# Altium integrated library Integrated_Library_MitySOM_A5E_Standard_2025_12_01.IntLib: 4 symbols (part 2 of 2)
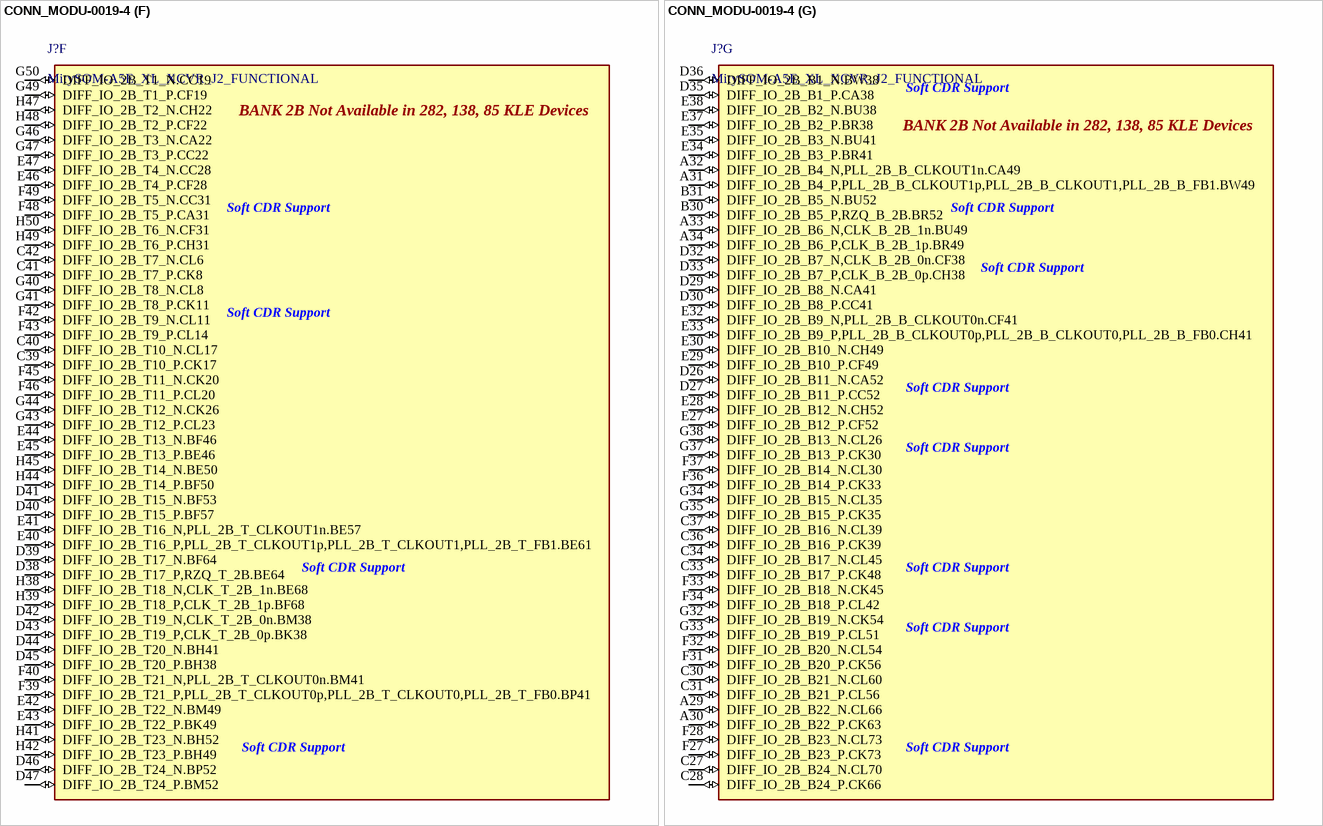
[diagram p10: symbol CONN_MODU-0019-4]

## CONN_MODU-0019-4
designator J?, comment MitySOM-A5E_XL_XCVR_J2_FUNCTIONAL
MitySOM-A5E  XL XCVR Interface Connector, J2, CONN HD ARRAY PLUG 400P SMD GOLD; Manuf 1: Samtec; Manuf 2_PN: SEAM-50-02.0-S-08-2-A-K-TR; Manuf 1_PN: SEAM-50-02.0-L-08-2-A-K-TR; Angle: Vertical; CLPN: 13059
footprint SEAM-50-02.0-S-08-2-A-K-TR (CONN ARRAY SOCKET 400 POS SMD)
part A pins: A01 GND (power), A04 GND (power), A05 GND (power), A08 GND (power), A09 GND (power), A12 GND (power), A13 GND (power), A16 GND (power), A17 GND (power), A20 GND (power), A25 GND (power), A28 GND (power), A35 GND (power), A38 GND (power), A39 GND (power), A42 GND (power), A43 GND (power), A46 GND (power), A47 GND (power), A50 GND (power), B03 GND (power), B06 GND (power), B07 GND (power), B10 GND (power), B11 GND (power), B14 GND (power), B15 GND (power), B18 GND (power), B23 GND (power), B26 GND (power), B29 GND (power), B32 GND (power), B33 GND (power), B36 GND (power), B37 GND (power), B40 GND (power), B41 GND (power), B44 GND (power), B45 GND (power), B48 GND (power), B49 GND (power), B50 GND (power), C01 GND (power), C04 GND (power), C05 GND (power), C08 GND (power), C11 GND (power), C14 GND (power), C17 GND (power), C20 GND (power), C23 GND (power), C26 GND (power), C29 GND (power), C32 GND (power), C35 GND (power), C38 GND (power), C43 GND (power), C46 GND (power), C47 GND (power), C50 GND (power), D03 GND (power), D10 GND (power), D13 GND (power), D16 GND (power), D19 GND (power), D22 GND (power), D25 GND (power), D28 GND (power), D31 GND (power), D34 GND (power), D37 GND (power), D48 GND (power), D49 GND (power), D50 GND (power), E03 GND (power), E06 GND (power), E09 GND (power), E12 GND (power), E15 GND (power), E18 GND (power), E31 GND (power), E36 GND (power), E39 GND (power), E48 GND (power), E49 GND (power), E50 GND (power), F01 GND (power), F08 GND (power), F11 GND (power), F14 GND (power), F17 GND (power), F18 GND (power), F21 GND (power), F22 GND (power), F25 GND (power), F26 GND (power), F29 GND (power), F30 GND (power), F35 GND (power), F38 GND (power), F41 GND (power), F44 GND (power), F47 GND (power), F50 GND (power), G05 GND (power), G08 GND (power), G15 GND (power), G16 GND (power), G19 GND (power), G20 GND (power), G23 GND (power), G24 GND (power), G27 GND (power), G28 GND (power), G31 GND (power), G36 GND (power), G39 GND (power), G42 GND (power), G45 GND (power), G48 GND (power), H02 GND (power), H05 GND (power), H08 GND (power), H11 GND (power), H14 GND (power), H17 GND (power), H18 GND (power), H21 GND (power), H22 GND (power), H25 GND (power), H26 GND (power), H29 GND (power), H30 GND (power), H33 GND (power), H34 GND (power), H37 GND (power), H40 GND (power), H43 GND (power), H46 GND (power)
part B pins: B01 VCCIO_2A (power), B02 VCCIO_2A (power), D01 VCCIO_2A (power), D02 VCCIO_2A (power), E01 VCCIO_2B (power), E02 VCCIO_2B (power), G01 VCCIO_2B (power), G02 VCCIO_2B (power), H01 FAN_EN (in)
part C pins: A02 GTSR4A_TX_CH0_P.BY7 (out), A03 GTSR4A_TX_CH0_N.BY10 (out), A06 GTSR4A_TX_CH1_P.BT7 (out), A07 GTSR4A_TX_CH1_N.BT10 (out), A10 GTSR4A_TX_CH2_P.BL7 (out), A11 GTSR4A_TX_CH2_N.BL10 (out), A14 GTSR4A_TX_CH3_P.BG7 (out), A15 GTSR4A_TX_CH3_N.BG10 (out), A18 REFCLK_GTSR4A_CH1_P.BB16 (in), A19 REFCLK_GTSR4A_CH1_N.BB21 (in), A36 GTSR4C_TX_CH0_P.AU7 (out), A37 GTSR4C_TX_CH0_N.AU10 (out), A40 GTSR4C_TX_CH1_P.AR7 (out), A41 GTSR4C_TX_CH1_N.AR10 (out), A44 GTSR4C_TX_CH2_P.AN7 (out), A45 GTSR4C_TX_CH2_N.AN10 (out), A48 GTSR4C_TX_CH3_P.AL7 (out), A49 GTSR4C_TX_CH3_N.AL10 (out), B04 GTSR4A_RX_CH0_P.CB1 (in), B05 GTSR4A_RX_CH0_N.CB3 (in), B08 GTSR4A_RX_CH1_P.BV1 (in), B09 GTSR4A_RX_CH1_N.BV3 (in), B12 GTSR4A_RX_CH2_P.BN1 (in), B13 GTSR4A_RX_CH2_N.BN3 (in), B16 GTSR4A_RX_CH3_P.BJ1 (in), B17 GTSR4A_RX_CH3_N.BJ3 (in), B34 GTSR4C_RX_CH0_P.AV1 (in), B35 GTSR4C_RX_CH0_N.AV3 (in), B38 GTSR4C_RX_CH1_P.AT1 (in), B39 GTSR4C_RX_CH1_N.AT3 (in), B42 GTSR4C_RX_CH2_P.AP1 (in), B43 GTSR4C_RX_CH2_N.AP3 (in), B46 GTSR4C_RX_CH3_P.AM1 (in), B47 GTSR4C_RX_CH3_N.AM3 (in), C02 REFCLK_GTSR4A_RX_P.BC29 (in), C03 REFCLK_GTSR4A_RX_N.BC25 (in), C44 REFCLK_GTSR4C_RX_P.AT16 (in), C45 REFCLK_GTSR4C_RX_N.AT21 (in), C48 REFCLK_GTSR4C_CH1_P.AP16 (in), C49 REFCLK_GTSR4C_CH1_N.AP21 (in), G17 GTSR4B_RX_CH0_P.BF1 (in), G18 GTSR4B_RX_CH0_N.BF3 (in), G21 GTSR4B_RX_CH1_P.BD1 (in), G22 GTSR4B_RX_CH1_N.BD3 (in), G25 GTSR4B_RX_CH2_P.BB1 (in), G26 GTSR4B_RX_CH2_N.BB3 (in), G29 GTSR4B_RX_CH3_P.AY1 (in), G30 GTSR4B_RX_CH3_N.AY3 (in), H15 REFCLK_GTSR4B_RX_P.AY16 (in), H16 REFCLK_GTSR4B_RX_N.AY21 (in), H19 GTSR4B_TX_CH0_P.BE7 (out), H20 GTSR4B_TX_CH0_N.BE10 (out), H23 GTSR4B_TX_CH1_P.BC7 (out), H24 GTSR4B_TX_CH1_N.BC10 (out), H27 GTSR4B_TX_CH2_P.BA7 (out), H28 GTSR4B_TX_CH2_N.BA10 (out), H31 GTSR4B_TX_CH3_P.AW7 (out), H32 GTSR4B_TX_CH3_N.AW10 (out), H35 REFCLK_GTSR4B_CH1_P.AV16 (in), H36 REFCLK_GTSR4B_CH1_N.AV21 (in)
part D pins: A21 DIFF_IO_2A_T2_P.CF62 (io), A22 DIFF_IO_2A_T2_N.CH62 (io), A23 DIFF_IO_2A_T9_N.BR62 (io), A24 DIFF_IO_2A_T9_P.BU62 (io), A26 DIFF_IO_2A_T17_P,RZQ_T_2A.BH69 (io), A27 DIFF_IO_2A_T17_N.BH71 (io), B19 DIFF_IO_2A_T14_N.BH59 (io), B20 DIFF_IO_2A_T14_P.BH62 (io), B21 DIFF_IO_2A_T15_P.BM62 (io), B22 DIFF_IO_2A_T15_N.BP62 (io), B24 DIFF_IO_2A_T16_P,PLL_2A_T_CLKOUT1p,PLL_2A_T_CLKOUT1,PLL_2A_T_FB1.BM69 (io), B25 DIFF_IO_2A_T16_N,PLL_2A_T_CLKOUT1n.BK69 (io), B27 DIFF_IO_2A_T21_N,PLL_2A_T_CLKOUT0n.BF83 (io), B28 DIFF_IO_2A_T21_P,PLL_2A_T_CLKOUT0p,PLL_2A_T_CLKOUT0,PLL_2A_T_FB0.BE83 (io), C15 DIFF_IO_2A_T5_N.CA71 (io), C16 DIFF_IO_2A_T5_P.CC71 (io), C18 DIFF_IO_2A_T10_N.CA69 (io), C19 DIFF_IO_2A_T10_P.BW69 (io), C21 DIFF_IO_2A_T1_P.CF59 (io), C22 DIFF_IO_2A_T1_N.CH59 (io), C24 DIFF_IO_2A_T7_N.CA59 (io), C25 DIFF_IO_2A_T7_P.BW59 (io), D17 DIFF_IO_2A_T11_P.BR71 (io), D18 DIFF_IO_2A_T11_N.BU71 (io), D20 DIFF_IO_2A_T20_N.BE75 (io), D21 DIFF_IO_2A_T20_P.BE79 (io), D23 DIFF_IO_2A_T19_P,CLK_T_2A_0p.BF75 (io), D24 DIFF_IO_2A_T19_N,CLK_T_2A_0n.BF72 (io), E16 DIFF_IO_2A_T13_N.BK59 (io), E17 DIFF_IO_2A_T13_P.BM59 (io), E19 DIFF_IO_2A_T12_P.BR69 (io), E20 DIFF_IO_2A_T12_N.BU69 (io), E21 DIFF_IO_2A_T3_P.CA62 (io), E22 DIFF_IO_2A_T3_N.CC62 (io), E23 DIFF_IO_2A_T23_N.BF90 (io), E24 DIFF_IO_2A_T23_P.BF93 (io), E25 DIFF_IO_2A_T24_N.BE93 (io), E26 DIFF_IO_2A_T24_P.BE96 (io), F15 DIFF_IO_2A_T6_P.CF71 (io), F16 DIFF_IO_2A_T6_N.CH71 (io), F19 DIFF_IO_2A_T4_N.CF69 (io), F20 DIFF_IO_2A_T4_P.CH69 (io), F23 DIFF_IO_2A_T8_N.BR59 (io), F24 DIFF_IO_2A_T8_P.BU59 (io), G11 DIFF_IO_2A_T18_P,CLK_T_2A_1p.BM71 (io), G12 DIFF_IO_2A_T18_N,CLK_T_2A_1n.BP71 (io), G13 DIFF_IO_2A_T22_N.BE86 (io), G14 DIFF_IO_2A_T22_P.BF86 (io)
part E pins: C06 DIFF_IO_2A_B12_N.BU89 (io), C07 DIFF_IO_2A_B12_P.BR89 (io), C09 DIFF_IO_2A_B10_N.CA89 (io), C10 DIFF_IO_2A_B10_P.BW89 (io), C12 DIFF_IO_2A_B15_P.CF81 (io), C13 DIFF_IO_2A_B15_N.CH81 (io), D04 DIFF_IO_2A_B11_P.BR92 (io), D05 DIFF_IO_2A_B11_N.BU92 (io), D06 DIFF_IO_2A_B16_N.CF89 (io), D07 DIFF_IO_2A_B16_P.CH89 (io), D08 DIFF_IO_2A_B3_P.BM81 (io), D09 DIFF_IO_2A_B3_N.BP81 (io), D11 DIFF_IO_2A_B14_P.CA81 (io), D12 DIFF_IO_2A_B14_N.CC81 (io), D14 DIFF_IO_2A_B7_N,CLK_B_2A_0n.CA78 (io), D15 DIFF_IO_2A_B7_P,CLK_B_2A_0p.BW78 (io), E04 DIFF_IO_2A_B5_N.BH92 (io), E05 DIFF_IO_2A_B5_P,RZQ_B_2A.BH89 (io), E07 DIFF_IO_2A_B1_P.BM78 (io), E08 DIFF_IO_2A_B1_N.BK78 (io), E10 DIFF_IO_2A_B13_N.CF78 (io), E11 DIFF_IO_2A_B13_P.CH78 (io), E13 DIFF_IO_2A_B8_N.BU78 (io), E14 DIFF_IO_2A_B8_P.BR78 (io), F02 DIFF_IO_2A_B6_N,CLK_B_2A_1n.BM92 (io), F03 DIFF_IO_2A_B6_P,CLK_B_2A_1p.BP92 (io), F04 DIFF_IO_2A_B4_N,PLL_2A_B_CLKOUT1n.BM89 (io), F05 DIFF_IO_2A_B4_P,PLL_2A_B_CLKOUT1p,PLL_2A_B_CLKOUT1,PLL_2A_B_FB1.BK89 (io), F06 DIFF_IO_2A_B2_P.BH81 (io), F07 DIFF_IO_2A_B2_N.BH78 (io), F09 DIFF_IO_2A_B9_N,PLL_2A_B_CLKOUT0n.BU81 (io), F10 DIFF_IO_2A_B9_P,PLL_2A_B_CLKOUT0p,PLL_2A_B_CLKOUT0,PLL_2A_B_FB0.BR81 (io), F12 DIFF_IO_2A_B17_P.CF92 (io), F13 DIFF_IO_2A_B17_N.CH92 (io), G03 DIFF_IO_2A_B23_N.CL97 (io), G04 DIFF_IO_2A_B23_P.CK97 (io), G06 DIFF_IO_2A_B22_N.CK88 (io), G07 DIFF_IO_2A_B22_P.CL88 (io), G09 DIFF_IO_2A_B18_N.CA92 (io), G10 DIFF_IO_2A_B18_P.CC92 (io), H03 DIFF_IO_2A_B24_N.CK94 (io), H04 DIFF_IO_2A_B24_P.CL91 (io), H06 DIFF_IO_2A_B21_N.CL85 (io), H07 DIFF_IO_2A_B21_P.CK85 (io), H09 DIFF_IO_2A_B20_N.CL82 (io), H10 DIFF_IO_2A_B20_P.CK80 (io), H12 DIFF_IO_2A_B19_P.CK76 (io), H13 DIFF_IO_2A_B19_N.CL76 (io)
part F pins: C39 DIFF_IO_2B_T10_P.CK17 (io), C40 DIFF_IO_2B_T10_N.CL17 (io), C41 DIFF_IO_2B_T7_P.CK8 (io), C42 DIFF_IO_2B_T7_N.CL6 (io), D38 DIFF_IO_2B_T17_P,RZQ_T_2B.BE64 (io), D39 DIFF_IO_2B_T17_N.BF64 (io), D40 DIFF_IO_2B_T15_P.BF57 (io), D41 DIFF_IO_2B_T15_N.BF53 (io), D42 DIFF_IO_2B_T19_N,CLK_T_2B_0n.BM38 (io), D43 DIFF_IO_2B_T19_P,CLK_T_2B_0p.BK38 (io), D44 DIFF_IO_2B_T20_N.BH41 (io), D45 DIFF_IO_2B_T20_P.BH38 (io), D46 DIFF_IO_2B_T24_N.BP52 (io), D47 DIFF_IO_2B_T24_P.BM52 (io), E40 DIFF_IO_2B_T16_P,PLL_2B_T_CLKOUT1p,PLL_2B_T_CLKOUT1,PLL_2B_T_FB1.BE61 (io), E41 DIFF_IO_2B_T16_N,PLL_2B_T_CLKOUT1n.BE57 (io), E42 DIFF_IO_2B_T22_N.BM49 (io), E43 DIFF_IO_2B_T22_P.BK49 (io), E44 DIFF_IO_2B_T13_N.BF46 (io), E45 DIFF_IO_2B_T13_P.BE46 (io), E46 DIFF_IO_2B_T4_P.CF28 (io), E47 DIFF_IO_2B_T4_N.CC28 (io), F39 DIFF_IO_2B_T21_P,PLL_2B_T_CLKOUT0p,PLL_2B_T_CLKOUT0,PLL_2B_T_FB0.BP41 (io), F40 DIFF_IO_2B_T21_N,PLL_2B_T_CLKOUT0n.BM41 (io), F42 DIFF_IO_2B_T9_N.CL11 (io), F43 DIFF_IO_2B_T9_P.CL14 (io), F45 DIFF_IO_2B_T11_N.CK20 (io), F46 DIFF_IO_2B_T11_P.CL20 (io), F48 DIFF_IO_2B_T5_P.CA31 (io), F49 DIFF_IO_2B_T5_N.CC31 (io), G40 DIFF_IO_2B_T8_N.CL8 (io), G41 DIFF_IO_2B_T8_P.CK11 (io), G43 DIFF_IO_2B_T12_P.CL23 (io), G44 DIFF_IO_2B_T12_N.CK26 (io), G46 DIFF_IO_2B_T3_N.CA22 (io), G47 DIFF_IO_2B_T3_P.CC22 (io), G49 DIFF_IO_2B_T1_P.CF19 (io), G50 DIFF_IO_2B_T1_N.CC19 (io), H38 DIFF_IO_2B_T18_N,CLK_T_2B_1n.BE68 (io), H39 DIFF_IO_2B_T18_P,CLK_T_2B_1p.BF68 (io), H41 DIFF_IO_2B_T23_N.BH52 (io), H42 DIFF_IO_2B_T23_P.BH49 (io), H44 DIFF_IO_2B_T14_P.BF50 (io), H45 DIFF_IO_2B_T14_N.BE50 (io), H47 DIFF_IO_2B_T2_N.CH22 (io), H48 DIFF_IO_2B_T2_P.CF22 (io), H49 DIFF_IO_2B_T6_P.CH31 (io), H50 DIFF_IO_2B_T6_N.CF31 (io)
part G pins: A29 DIFF_IO_2B_B22_N.CL66 (io), A30 DIFF_IO_2B_B22_P.CK63 (io), A31 DIFF_IO_2B_B4_P,PLL_2B_B_CLKOUT1p,PLL_2B_B_CLKOUT1,PLL_2B_B_FB1.BW49 (io), A32 DIFF_IO_2B_B4_N,PLL_2B_B_CLKOUT1n.CA49 (io), A33 DIFF_IO_2B_B6_N,CLK_B_2B_1n.BU49 (io), A34 DIFF_IO_2B_B6_P,CLK_B_2B_1p.BR49 (io), B30 DIFF_IO_2B_B5_P,RZQ_B_2B.BR52 (io), B31 DIFF_IO_2B_B5_N.BU52 (io), C27 DIFF_IO_2B_B24_N.CL70 (io), C28 DIFF_IO_2B_B24_P.CK66 (io), C30 DIFF_IO_2B_B21_N.CL60 (io), C31 DIFF_IO_2B_B21_P.CL56 (io), C33 DIFF_IO_2B_B17_P.CK48 (io), C34 DIFF_IO_2B_B17_N.CL45 (io), C36 DIFF_IO_2B_B16_P.CK39 (io), C37 DIFF_IO_2B_B16_N.CL39 (io), D26 DIFF_IO_2B_B11_N.CA52 (io), D27 DIFF_IO_2B_B11_P.CC52 (io), D29 DIFF_IO_2B_B8_N.CA41 (io), D30 DIFF_IO_2B_B8_P.CC41 (io), D32 DIFF_IO_2B_B7_N,CLK_B_2B_0n.CF38 (io), D33 DIFF_IO_2B_B7_P,CLK_B_2B_0p.CH38 (io), D35 DIFF_IO_2B_B1_P.CA38 (io), D36 DIFF_IO_2B_B1_N.BW38 (io), E27 DIFF_IO_2B_B12_P.CF52 (io), E28 DIFF_IO_2B_B12_N.CH52 (io), E29 DIFF_IO_2B_B10_P.CF49 (io), E30 DIFF_IO_2B_B10_N.CH49 (io), E32 DIFF_IO_2B_B9_N,PLL_2B_B_CLKOUT0n.CF41 (io), E33 DIFF_IO_2B_B9_P,PLL_2B_B_CLKOUT0p,PLL_2B_B_CLKOUT0,PLL_2B_B_FB0.CH41 (io), E34 DIFF_IO_2B_B3_P.BR41 (io), E35 DIFF_IO_2B_B3_N.BU41 (io), E37 DIFF_IO_2B_B2_P.BR38 (io), E38 DIFF_IO_2B_B2_N.BU38 (io), F27 DIFF_IO_2B_B23_P.CK73 (io), F28 DIFF_IO_2B_B23_N.CL73 (io), F31 DIFF_IO_2B_B20_P.CK56 (io), F32 DIFF_IO_2B_B20_N.CL54 (io), F33 DIFF_IO_2B_B18_N.CK45 (io), F34 DIFF_IO_2B_B18_P.CL42 (io), F36 DIFF_IO_2B_B14_P.CK33 (io), F37 DIFF_IO_2B_B14_N.CL30 (io), G32 DIFF_IO_2B_B19_N.CK54 (io), G33 DIFF_IO_2B_B19_P.CL51 (io), G34 DIFF_IO_2B_B15_N.CL35 (io), G35 DIFF_IO_2B_B15_P.CK35 (io), G37 DIFF_IO_2B_B13_P.CK30 (io), G38 DIFF_IO_2B_B13_N.CL26 (io)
